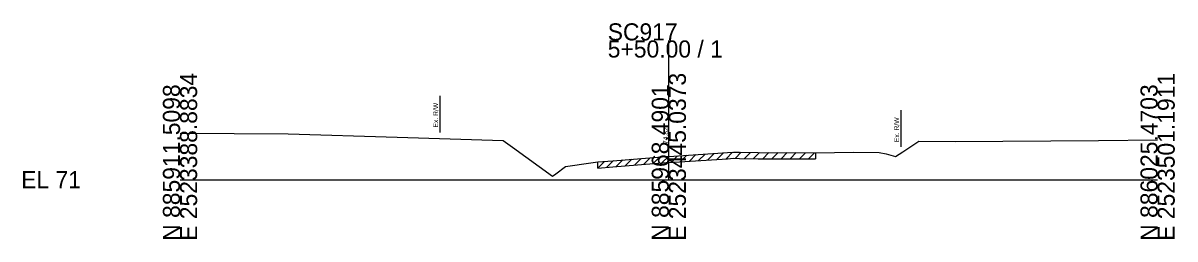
# Model space of a CAD drawing. Extents: x -26 to 218, y -10 to 12021.
# Drawn here: x -25.7 to 162.8, y 5490.3 to 5525.6 of the extents above; entities that cross this region are included whole.
import ezdxf

# ---------------------------------------------------------------- set-up
doc = ezdxf.new("R2010")
doc.units = 0
for name, color, linetype in [('RD_GPK_XS_Cell', 7, 'Continuous'), ('RD_XS_ExGround', 7, 'Continuous'), ('RD_XS_ExPaveRet', 7, 'Continuous'), ('RD_XS_ExRW', 7, 'Continuous'), ('RD_XS_TX_Elev_EX', 7, 'Continuous')]:
    doc.layers.add(name, color=color, linetype=linetype)

msp = doc.modelspace()

# ---------------------------------------------------------------- linework, layer by layer
at = {"layer": 'RD_GPK_XS_Cell'}
for p, q in [((80, 5500), (80, 5522.79)), ((0, 5500), (80, 5500)), ((80, 5500), (160, 5500))]:
    msp.add_line(p, q, dxfattribs=at)
at = {"layer": 'RD_XS_ExGround'}
for p, q in [((0, 5507.6), (17.69, 5507.49)), ((17.69, 5507.49), (35.56, 5506.96)), ((35.56, 5506.96), (52.9, 5506.44)), ((52.9, 5506.44), (54.42, 5505.35)), ((54.42, 5505.35), (60.97, 5500.59)), ((118.28, 5504.58), (120.9, 5506.3)), ((120.9, 5506.3), (126.87, 5506.27)), ((126.87, 5506.27), (150.33, 5506.39)), ((150.33, 5506.39), (160, 5506.53)), ((70.82, 5503.11), (79.54, 5503.79)), ((79.54, 5503.79), (80, 5503.82)), ((80, 5503.82), (89.62, 5504.44)), ((89.62, 5504.44), (90.58, 5504.5)), ((90.58, 5504.5), (91.58, 5504.49)), ((91.58, 5504.49), (94.62, 5504.44)), ((94.62, 5504.44), (104.02, 5504.42)), ((104.02, 5504.42), (110.24, 5504.51)), ((110.24, 5504.51), (114.44, 5504.46)), ((114.44, 5504.46), (115.59, 5504.22)), ((115.59, 5504.22), (117.12, 5503.8)), ((117.12, 5503.8), (118.28, 5504.58)), ((61.5, 5500.96), (63.07, 5502.18)), ((63.07, 5502.18), (67.26, 5502.76)), ((67.26, 5502.76), (68.37, 5502.91)), ((68.37, 5502.91), (70.82, 5503.11)), ((60.97, 5500.59), (61.5, 5500.96))]:
    msp.add_line(p, q, dxfattribs=at)
at = {"layer": 'RD_XS_ExPaveRet'}
for p, q in [((72.87, 5502.27), (73.96, 5503.35)), ((74.37, 5502.39), (75.46, 5503.47)), ((75.87, 5502.5), (76.96, 5503.59)), ((77.37, 5502.62), (78.46, 5503.71)), ((78.87, 5502.74), (79.95, 5503.82)), ((80, 5502.82), (89.62, 5503.44)), ((80.37, 5502.84), (81.44, 5503.91)), ((81.87, 5502.94), (82.94, 5504.01)), ((83.37, 5503.04), (84.44, 5504.1)), ((84.87, 5503.13), (85.94, 5504.2)), ((86.37, 5503.23), (87.44, 5504.3)), ((87.87, 5503.32), (88.94, 5504.39)), ((89.37, 5503.42), (90.44, 5504.49)), ((89.62, 5503.44), (90.58, 5503.5)), ((90.58, 5503.5), (91.58, 5503.49)), ((90.87, 5503.49), (91.86, 5504.49)), ((91.58, 5503.49), (94.62, 5503.44)), ((92.37, 5503.48), (93.36, 5504.46)), ((93.87, 5503.46), (94.86, 5504.44)), ((94.62, 5503.44), (104.02, 5503.42)), ((95.37, 5503.44), (96.37, 5504.44)), ((96.87, 5503.44), (97.87, 5504.44)), ((98.37, 5503.43), (99.37, 5504.43)), ((99.87, 5503.43), (100.87, 5504.43)), ((101.37, 5503.43), (102.37, 5504.42)), ((102.87, 5503.42), (103.87, 5504.42)), ((104.02, 5504.42), (104.02, 5503.42)), ((68.37, 5501.91), (69.46, 5503)), ((68.37, 5501.91), (68.37, 5502.91)), ((68.37, 5501.91), (70.82, 5502.11)), ((69.87, 5502.03), (70.96, 5503.12)), ((70.82, 5502.11), (79.54, 5502.79)), ((71.37, 5502.15), (72.46, 5503.24)), ((79.54, 5502.79), (80, 5502.82))]:
    msp.add_line(p, q, dxfattribs=at)
at = {"layer": 'RD_XS_ExRW'}
for p, q in [((42.5, 5513.75), (42.5, 5507.75)), ((117.95, 5511.36), (117.95, 5505.36))]:
    msp.add_line(p, q, dxfattribs=at)

# ---------------------------------------------------------------- texts
at = {"layer": 'RD_GPK_XS_Cell'}
for s, p in [('SC917', (70, 5522.79)), ('5+50.00 / 1', (70, 5519.99)), ('EL 71', (-26, 5498.6))]:
    msp.add_text(s, height=2.8, dxfattribs=at).set_placement(p)
for s, p in [('E 2523388.8834', (2.8, 5490)), ('E 2523445.0373', (82.8, 5490)), ('E 2523501.1911', (162.8, 5490)), ('N 885911.5098', (0, 5490)), ('N 885968.4901', (80, 5490)), ('N 886025.4703', (160, 5490))]:
    msp.add_text(s, height=2.8, rotation=90, dxfattribs=at).set_placement(p)
at = {"layer": 'RD_XS_ExRW'}
for p in [(42.25, 5508.54), (117.7, 5506.15)]:
    msp.add_text('Ex. R/W ', height=0.8, rotation=90, dxfattribs=at).set_placement(p)
at = {"layer": 'RD_XS_TX_Elev_EX'}
msp.add_text('74.82', height=0.8, rotation=90, dxfattribs=at).set_placement((79.9, 5505.82))

doc.saveas('drawing.dxf')
